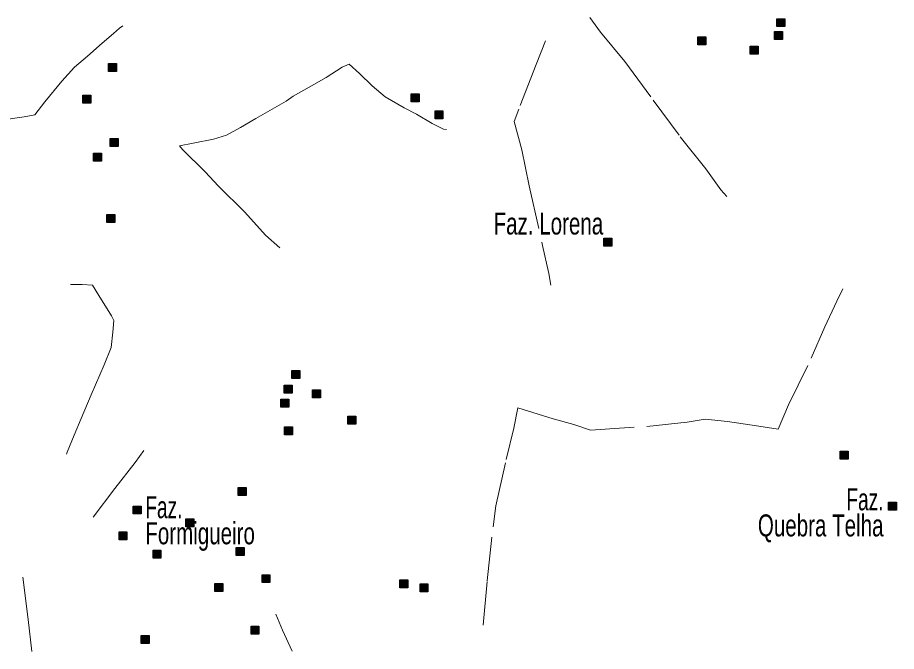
# Model space of a CAD drawing. Extents: x 445.6 to 500, y 8618.1 to 8673.4.
# Drawn here: x 463.29 to 469.69, y 8618.12 to 8622.73 of the extents above; entities that cross this region are included whole.
import ezdxf
from ezdxf.enums import TextEntityAlignment as Align

# ---------------------------------------------------------------- set-up
doc = ezdxf.new("R2010")
doc.units = 0
doc.header["$LTSCALE"] = 0.064
doc.linetypes.add('DOT_DASHED', pattern=[7.7, 5, -1.2, 0.3, -1.2])
doc.layers.add('2', color=7, linetype='Continuous', lineweight=25)
doc.layers.add('22', color=7, linetype='DOT_DASHED', lineweight=13)
doc.layers.add('61', color=7, linetype='Continuous')

msp = doc.modelspace()

# ---------------------------------------------------------------- hatches: boundary and pattern name
at = {"layer": '2'}
for points in [[(468.8231, 8622.7262), (468.8811, 8622.7262), (468.8811, 8622.6682), (468.8231, 8622.6682)], [(468.8065, 8622.6318), (468.8645, 8622.6318), (468.8645, 8622.5738), (468.8065, 8622.5738)], [(468.2468, 8622.5929), (468.3048, 8622.5929), (468.3048, 8622.5349), (468.2468, 8622.5349)], [(468.6292, 8622.5262), (468.6872, 8622.5262), (468.6872, 8622.4682), (468.6292, 8622.4682)], [(463.9507, 8622.4003), (464.0087, 8622.4003), (464.0087, 8622.3423), (463.9507, 8622.3423)], [(463.7632, 8622.1686), (463.8212, 8622.1686), (463.8212, 8622.1106), (463.7632, 8622.1106)], [(466.157, 8622.1787), (466.215, 8622.1787), (466.215, 8622.1207), (466.157, 8622.1207)], [(466.3311, 8622.0544), (466.3891, 8622.0544), (466.3891, 8621.9964), (466.3311, 8621.9964)], [(463.9624, 8621.853), (464.0204, 8621.853), (464.0204, 8621.795), (463.9624, 8621.795)], [(463.8419, 8621.7456), (463.8999, 8621.7456), (463.8999, 8621.6876), (463.8419, 8621.6876)], [(463.939, 8621.299), (463.997, 8621.299), (463.997, 8621.241), (463.939, 8621.241)], [(467.5628, 8621.1275), (467.6208, 8621.1275), (467.6208, 8621.0695), (467.5628, 8621.0695)], [(465.2877, 8620.1636), (465.3457, 8620.1636), (465.3457, 8620.1056), (465.2877, 8620.1056)], [(465.2308, 8620.0561), (465.2888, 8620.0561), (465.2888, 8619.9981), (465.2308, 8619.9981)], [(465.439, 8620.0214), (465.497, 8620.0214), (465.497, 8619.9634), (465.439, 8619.9634)], [(465.2073, 8619.9554), (465.2653, 8619.9554), (465.2653, 8619.8974), (465.2073, 8619.8974)], [(465.6961, 8619.8311), (465.7541, 8619.8311), (465.7541, 8619.7731), (465.6961, 8619.7731)], [(465.2341, 8619.7539), (465.2921, 8619.7539), (465.2921, 8619.6959), (465.2341, 8619.6959)], [(469.285, 8619.5761), (469.343, 8619.5761), (469.343, 8619.5181), (469.285, 8619.5181)], [(464.896, 8619.3106), (464.954, 8619.3106), (464.954, 8619.2526), (464.896, 8619.2526)], [(464.1314, 8619.1763), (464.1894, 8619.1763), (464.1894, 8619.1183), (464.1314, 8619.1183)], [(469.6365, 8619.2033), (469.6945, 8619.2033), (469.6945, 8619.1453), (469.6365, 8619.1453)], [(464.5143, 8619.0823), (464.5723, 8619.0823), (464.5723, 8619.0243), (464.5143, 8619.0243)], [(464.0276, 8618.9883), (464.0856, 8618.9883), (464.0856, 8618.9303), (464.0276, 8618.9303)], [(464.2754, 8618.8539), (464.3334, 8618.8539), (464.3334, 8618.7959), (464.2754, 8618.7959)], [(464.8826, 8618.8741), (464.9406, 8618.8741), (464.9406, 8618.8161), (464.8826, 8618.8161)], [(465.0701, 8618.676), (465.1281, 8618.676), (465.1281, 8618.618), (465.0701, 8618.618)], [(464.7252, 8618.6122), (464.7832, 8618.6122), (464.7832, 8618.5542), (464.7252, 8618.5542)], [(466.0744, 8618.639), (466.1324, 8618.639), (466.1324, 8618.581), (466.0744, 8618.581)], [(466.2217, 8618.6088), (466.2797, 8618.6088), (466.2797, 8618.5508), (466.2217, 8618.5508)], [(464.9897, 8618.2999), (465.0477, 8618.2999), (465.0477, 8618.2419), (464.9897, 8618.2419)], [(464.1883, 8618.2327), (464.2463, 8618.2327), (464.2463, 8618.1747), (464.1883, 8618.1747)]]:
    msp.add_hatch(color=256, dxfattribs=at).paths.add_polyline_path(points)

# ---------------------------------------------------------------- linework, layer by layer
for points in [[(468.8231, 8622.7262), (468.8811, 8622.7262), (468.8811, 8622.6682), (468.8231, 8622.6682)], [(468.8065, 8622.6318), (468.8645, 8622.6318), (468.8645, 8622.5738), (468.8065, 8622.5738)], [(468.2468, 8622.5929), (468.3048, 8622.5929), (468.3048, 8622.5349), (468.2468, 8622.5349)], [(468.6292, 8622.5262), (468.6872, 8622.5262), (468.6872, 8622.4682), (468.6292, 8622.4682)], [(463.9507, 8622.4003), (464.0087, 8622.4003), (464.0087, 8622.3423), (463.9507, 8622.3423)], [(463.7632, 8622.1686), (463.8212, 8622.1686), (463.8212, 8622.1106), (463.7632, 8622.1106)], [(466.157, 8622.1787), (466.215, 8622.1787), (466.215, 8622.1207), (466.157, 8622.1207)], [(466.3311, 8622.0544), (466.3891, 8622.0544), (466.3891, 8621.9964), (466.3311, 8621.9964)], [(463.9624, 8621.853), (464.0204, 8621.853), (464.0204, 8621.795), (463.9624, 8621.795)], [(463.8419, 8621.7456), (463.8999, 8621.7456), (463.8999, 8621.6876), (463.8419, 8621.6876)], [(463.939, 8621.299), (463.997, 8621.299), (463.997, 8621.241), (463.939, 8621.241)], [(467.5628, 8621.1275), (467.6208, 8621.1275), (467.6208, 8621.0695), (467.5628, 8621.0695)], [(465.2877, 8620.1636), (465.3457, 8620.1636), (465.3457, 8620.1056), (465.2877, 8620.1056)], [(465.2308, 8620.0561), (465.2888, 8620.0561), (465.2888, 8619.9981), (465.2308, 8619.9981)], [(465.439, 8620.0214), (465.497, 8620.0214), (465.497, 8619.9634), (465.439, 8619.9634)], [(465.2073, 8619.9554), (465.2653, 8619.9554), (465.2653, 8619.8974), (465.2073, 8619.8974)], [(465.6961, 8619.8311), (465.7541, 8619.8311), (465.7541, 8619.7731), (465.6961, 8619.7731)], [(465.2341, 8619.7539), (465.2921, 8619.7539), (465.2921, 8619.6959), (465.2341, 8619.6959)], [(469.285, 8619.5761), (469.343, 8619.5761), (469.343, 8619.5181), (469.285, 8619.5181)], [(464.896, 8619.3106), (464.954, 8619.3106), (464.954, 8619.2526), (464.896, 8619.2526)], [(464.1314, 8619.1763), (464.1894, 8619.1763), (464.1894, 8619.1183), (464.1314, 8619.1183)], [(469.6365, 8619.2033), (469.6945, 8619.2033), (469.6945, 8619.1453), (469.6365, 8619.1453)], [(464.5143, 8619.0823), (464.5723, 8619.0823), (464.5723, 8619.0243), (464.5143, 8619.0243)], [(464.0276, 8618.9883), (464.0856, 8618.9883), (464.0856, 8618.9303), (464.0276, 8618.9303)], [(464.2754, 8618.8539), (464.3334, 8618.8539), (464.3334, 8618.7959), (464.2754, 8618.7959)], [(464.8826, 8618.8741), (464.9406, 8618.8741), (464.9406, 8618.8161), (464.8826, 8618.8161)], [(465.0701, 8618.676), (465.1281, 8618.676), (465.1281, 8618.618), (465.0701, 8618.618)], [(464.7252, 8618.6122), (464.7832, 8618.6122), (464.7832, 8618.5542), (464.7252, 8618.5542)], [(466.0744, 8618.639), (466.1324, 8618.639), (466.1324, 8618.581), (466.0744, 8618.581)], [(466.2217, 8618.6088), (466.2797, 8618.6088), (466.2797, 8618.5508), (466.2217, 8618.5508)], [(464.9897, 8618.2999), (465.0477, 8618.2999), (465.0477, 8618.2419), (464.9897, 8618.2419)], [(464.1883, 8618.2327), (464.2463, 8618.2327), (464.2463, 8618.1747), (464.1883, 8618.1747)]]:
    msp.add_lwpolyline(points, close=True, dxfattribs=at)
at = {"layer": '22'}
for points in [[(467.4599, 8622.7341), (467.5378, 8622.6268), (467.7152, 8622.4149), (467.9205, 8622.1335), (468.1188, 8621.866), (468.3041, 8621.6312), (468.4154, 8621.4784), (468.4571, 8621.4299)], [(462.7775, 8621.932), (462.9542, 8621.9507), (463.1857, 8621.9883), (463.3362, 8622.0114), (463.4144, 8622.0259), (463.4867, 8622.1213), (463.6112, 8622.2715), (463.7038, 8622.3727), (463.7973, 8622.4524), (463.9043, 8622.5478), (463.9883, 8622.6171), (464.0317, 8622.6576), (464.0553, 8622.6751)], [(467.1367, 8622.5654), (467.0672, 8622.3935), (466.942, 8622.067), (466.9072, 8621.9766), (466.9629, 8621.7717), (467.0181, 8621.5088), (467.1155, 8621.0746), (467.1608, 8620.8696), (467.1748, 8620.7858)], [(465.1998, 8621.0575), (465.0963, 8621.1501), (464.9457, 8621.316), (464.7535, 8621.5053), (464.6548, 8621.6117), (464.4907, 8621.7737), (464.4673, 8621.7996), (464.5686, 8621.8204), (464.7166, 8621.8489), (464.8101, 8621.8774), (464.914, 8621.9345), (465.0257, 8621.9993), (465.2472, 8622.125), (465.2965, 8622.1613), (465.4134, 8622.2261), (465.538, 8622.2987), (465.6549, 8622.3739), (465.7042, 8622.3947), (465.7796, 8622.3273), (465.8731, 8622.2365), (465.9665, 8622.1561), (466.1068, 8622.0757), (466.1951, 8622.0316), (466.311, 8621.9636), (466.3941, 8621.9222), (466.4143, 8621.9184)], [(463.675, 8620.7904), (463.7593, 8620.7894), (463.835, 8620.7848), (463.8809, 8620.7092), (463.9726, 8620.5604), (463.9886, 8620.5284), (463.9818, 8620.4414), (463.9708, 8620.3297), (463.9204, 8620.2038), (463.824, 8619.9863), (463.7507, 8619.8145), (463.6994, 8619.6917), (463.649, 8619.5681), (463.6444, 8619.5544)], [(466.6821, 8618.3076), (466.7111, 8618.6315), (466.7545, 8619.0248), (466.7748, 8619.1781), (466.8504, 8619.5155), (466.9054, 8619.744), (466.9344, 8619.8915), (467.1921, 8619.8105), (467.3427, 8619.77), (467.4643, 8619.7295), (467.8755, 8619.7555), (468.168, 8619.7874), (468.3002, 8619.8089), (468.4623, 8619.7915), (468.6911, 8619.7568), (468.833, 8619.7366), (468.9083, 8619.913), (469.0741, 8620.2529), (469.1725, 8620.4814), (469.2594, 8620.6694), (469.303, 8620.7571)], [(463.8391, 8619.096), (463.9982, 8619.3047), (464.1456, 8619.4925), (464.2083, 8619.5808)], [(463.3259, 8618.6591), (463.3665, 8618.3489), (463.3926, 8618.1171)], [(465.1697, 8618.3883), (465.2189, 8618.2717), (465.289, 8618.1194)]]:
    msp.add_lwpolyline(points, dxfattribs=at)

# ---------------------------------------------------------------- texts
at = {"layer": '61'}
for s, width, p in [('Faz. Lorena', 0.7, (467.5571, 8621.1539)), ('Faz.', 0.65, (469.6003, 8619.1449)), ('Quebra Telha', 0.7, (469.6003, 8618.9549))]:
    msp.add_text(s, height=0.16, dxfattribs=dict(at, width=width)).set_placement(p, align=Align.RIGHT)
for s, width, p in [('Faz.', 0.65, (464.2191, 8619.0875)), ('Formigueiro', 0.7, (464.2191, 8618.8975))]:
    msp.add_text(s, height=0.16, dxfattribs=dict(at, width=width)).set_placement(p)

doc.saveas('drawing.dxf')
